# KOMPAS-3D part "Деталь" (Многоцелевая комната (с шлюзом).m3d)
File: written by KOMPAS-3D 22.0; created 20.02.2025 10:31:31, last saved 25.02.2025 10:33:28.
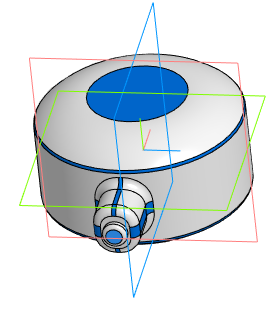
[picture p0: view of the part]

Document properties: Автор: Пользователь Windows; Полное имя файла: C:\Users\Student\Documents\Картошечка\База Сабнатика\Многоцелевая комната\Многоцелевая комната (с шлюзом).m3d

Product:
- Part/product: Деталь
    Масса: 0.431086

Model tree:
1. Эскиз:3
2. Элемент вращения:1
     Угол 1 = 360
3. Скругление:1  (with: Элемент вращения:1)
     Радиус = 1
4. Эскиз:4
5. Элемент выдавливания:1
     Расстояние 1 = 32.5
6. Скругление:3  (with: Элемент выдавливания:1)
     Радиус = 2
7. Элемент выдавливания:2  (with: Элемент выдавливания:1)
     Расстояние 1 = 3
8. Скругление:4  (with: Элемент выдавливания:2)
     Радиус = 2
9. Эскиз:5  (with: Элемент выдавливания:2)
10. Элемент выдавливания:3
     Расстояние 1 = 2
11. Скругление:5  (with: Элемент выдавливания:3)
     Радиус = 1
